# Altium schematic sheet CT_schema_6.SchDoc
size 385 x 355 mm
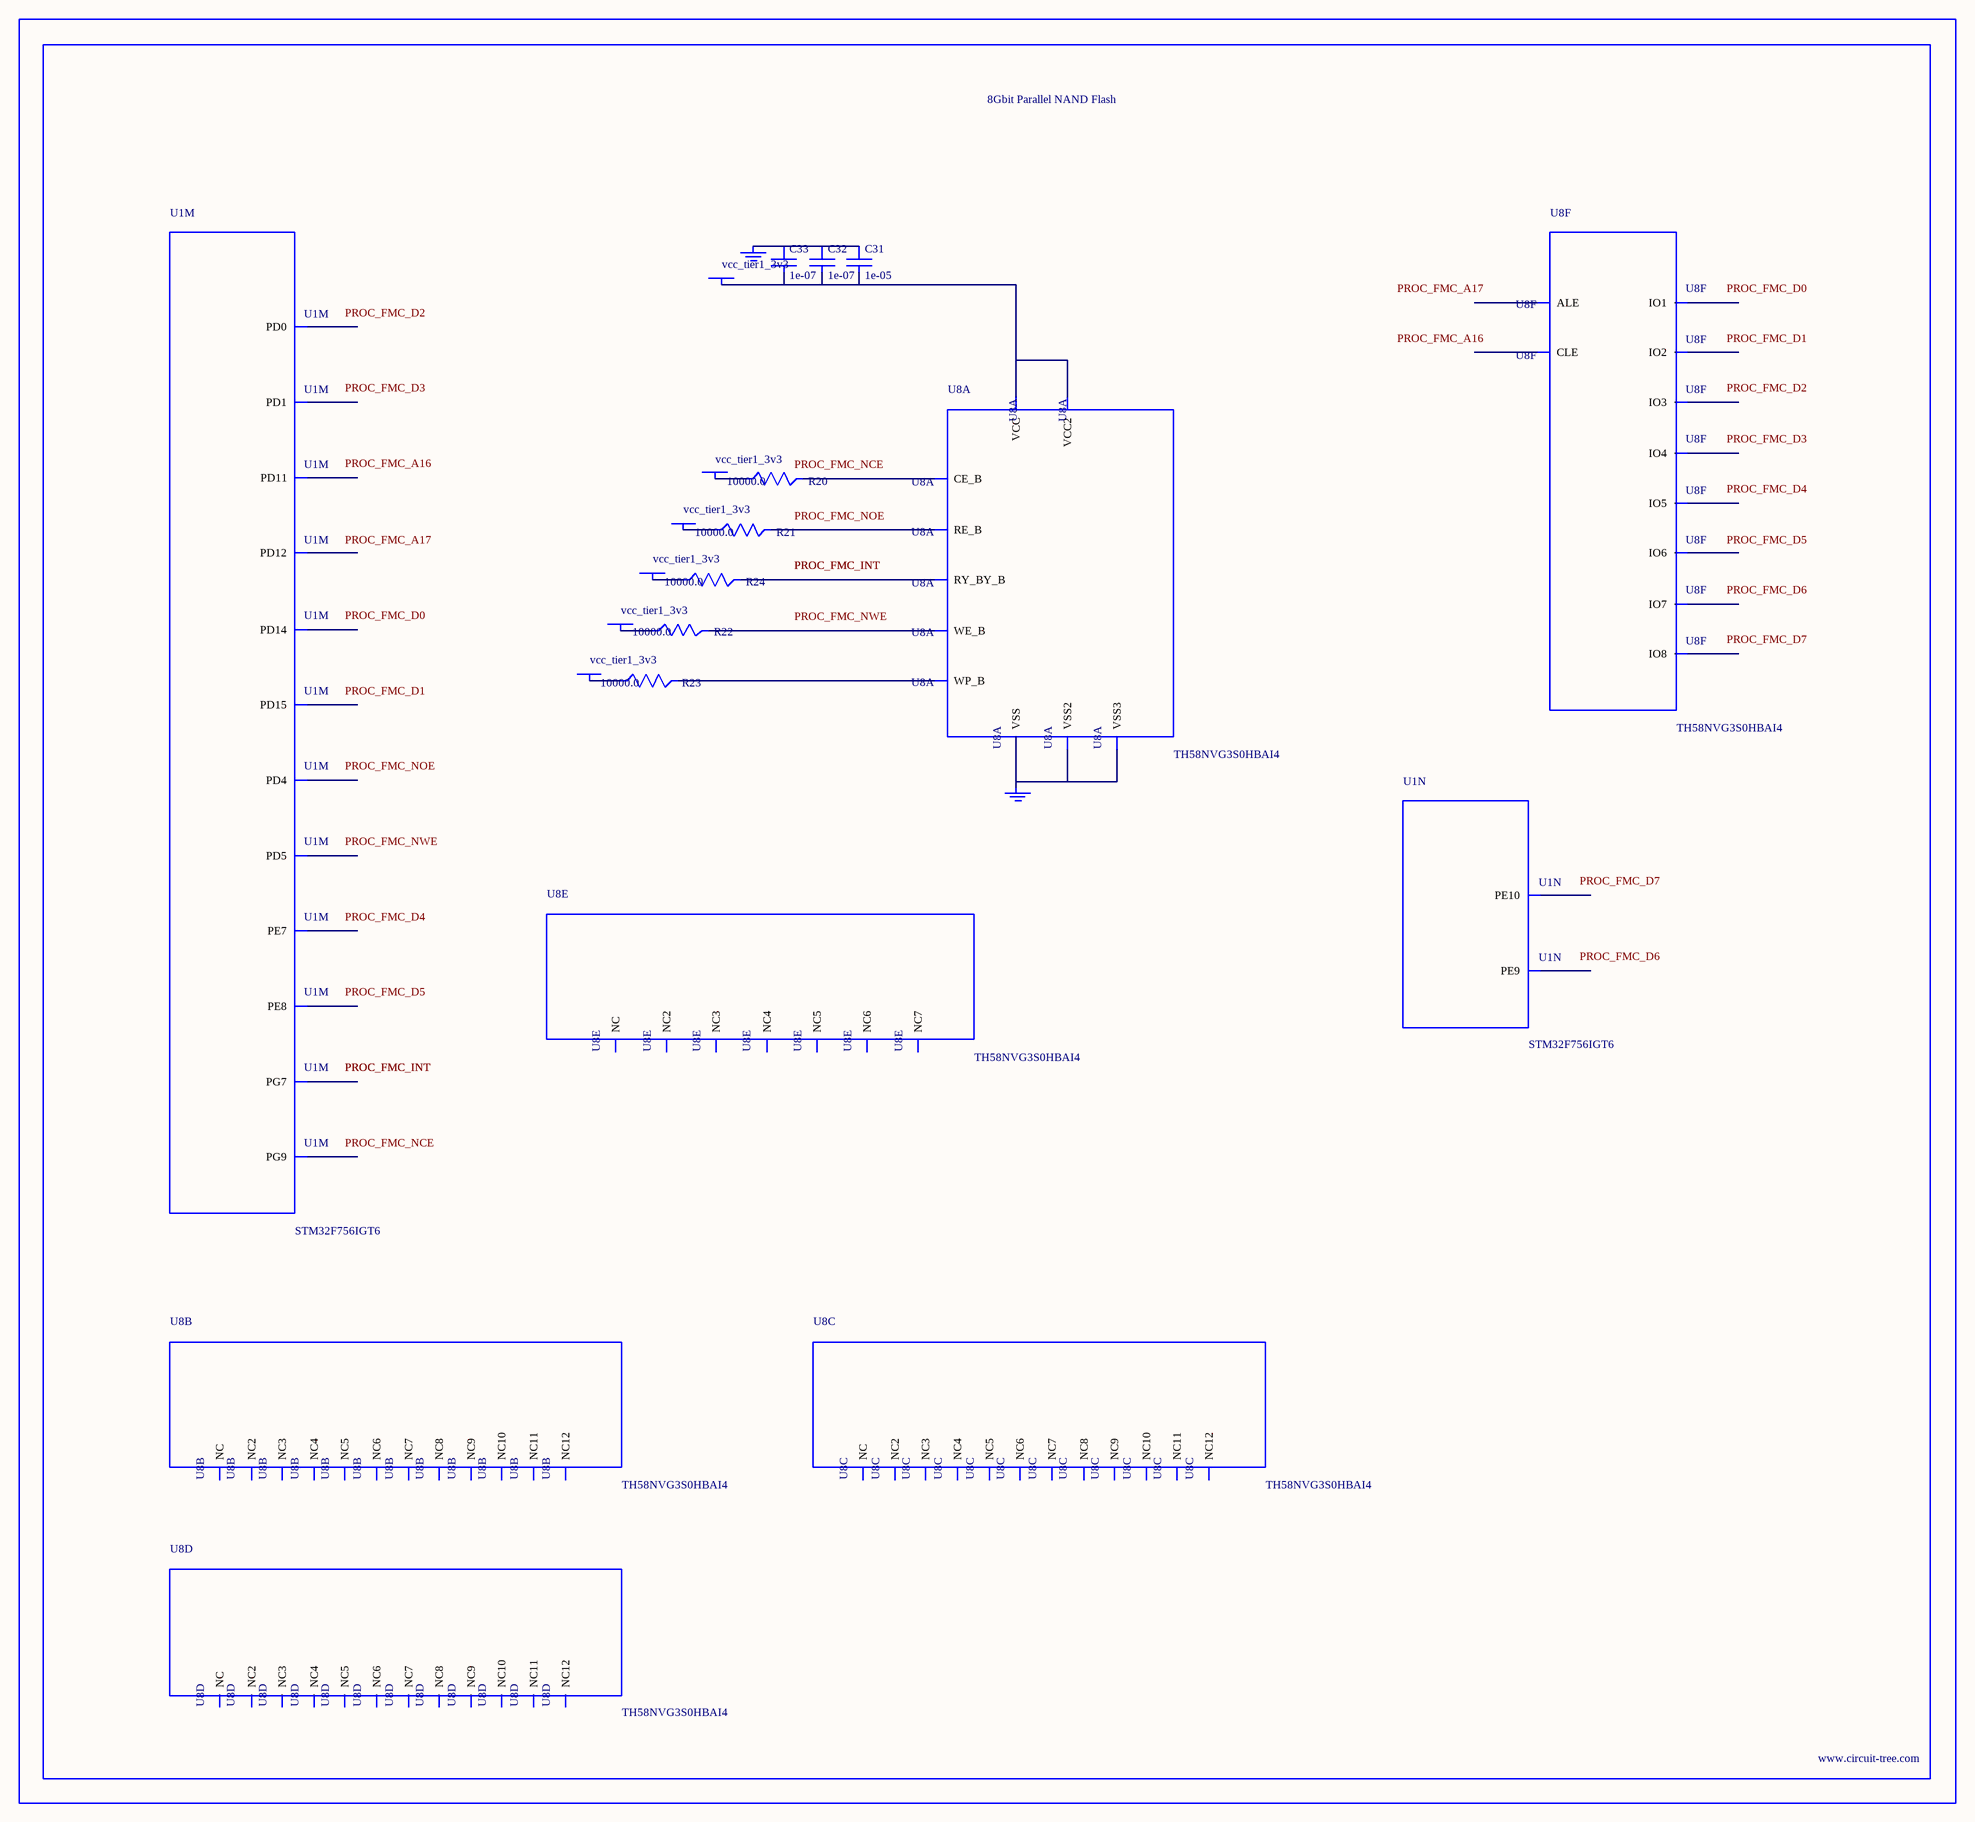
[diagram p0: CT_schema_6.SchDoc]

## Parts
BORDER5  (no value)
C31  1e-05  [C0805]
C32  1e-07  [C0402]
C33  1e-07  [C0402]
GND_INSTANCE_5_0  (no value)
GND_INSTANCE_5_1  (no value)
POWER_INSTANCE_5_0  vcc_tier1_3v3
POWER_INSTANCE_5_1  vcc_tier1_3v3
POWER_INSTANCE_5_2  vcc_tier1_3v3
POWER_INSTANCE_5_3  vcc_tier1_3v3
POWER_INSTANCE_5_4  vcc_tier1_3v3
POWER_INSTANCE_5_5  vcc_tier1_3v3
R20  10000.0  [R0603]
R21  10000.0  [R0603]
R22  10000.0  [R0603]
R23  10000.0  [R0603]
R24  10000.0  [R0603]
U1  STM32F756IGT6  [LQFP176]  (parts M,N of 14)
U8  TH58NVG3S0HBAI4  [TH58NVG3S0HBAI4]  (parts A,B,C,D,E,F of 6)

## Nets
NetC31_1: C31.1 C32.1 C33.1 GND_INSTANCE_5_0.0(GND)
NetC31_2: C31.2 C32.2 C33.2 POWER_INSTANCE_5_5.0(PWR) U8.H8(VCC) U8.J6(VCC2)
NetGND_INSTANCE_5_1_0: GND_INSTANCE_5_1.0(GND) U8.C5(VSS) U8.K3(VSS2) U8.K8(VSS3)
NetPOWER_INSTANCE_5_0_0: POWER_INSTANCE_5_0.0(PWR) R20.1
NetPOWER_INSTANCE_5_1_0: POWER_INSTANCE_5_1.0(PWR) R21.1
NetPOWER_INSTANCE_5_2_0: POWER_INSTANCE_5_2.0(PWR) R22.1
NetPOWER_INSTANCE_5_3_0: POWER_INSTANCE_5_3.0(PWR) R23.1
NetPOWER_INSTANCE_5_4_0: POWER_INSTANCE_5_4.0(PWR) R24.1
NetR20_2: R20.2 U8.C6(CE_B)
NetR21_2: R21.2 U8.D4(RE_B)
NetR22_2: R22.2 U8.C7(WE_B)
NetR23_2: R23.2 U8.C3(WP_B)
NetR24_2: R24.2 U8.C8(RY_BY_B)

Not connected (* = marked no-connect by the designer): U1 68(PE7) 69(PE8) 70(PE9) 73(PE10) 99(PD11) 100(PD12) 104(PD14) 105(PD15) 111(PG7) 142(PD0) 143(PD1) 146(PD4) 147(PD5) 152(PG9); U8 A1(NC) A2(NC3) A9(NC4) A10(NC2) B1(NC5) B9(NC7) B10(NC6) C4(ALE) D3(NC8) D5(CLE) D6(NC9) D7(NC10) D8(NC11) E3(NC12) E4(NC) E5(NC2) E6(NC3) E7(NC4) E8(NC5) F3(NC6) F4(NC7) F5(NC8) F6(NC9) F7(NC10) F8(NC11) G3(NC12) G4(NC) G5(NC2) G6(NC3) G7(NC4) G8(NC5) H3(NC6) H4(IO1) H5(NC7) H6(NC8) H7(NC9) J3(NC10) J4(IO2) J5(NC11) J7(IO6) J8(IO8) K4(IO3) K5(IO4) K6(IO5) K7(IO7) L1(NC12) L2(NC2) L9(NC3) L10(NC) M1(NC4) M2(NC6) M9(NC7) M10(NC5)

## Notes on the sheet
- Labels drawn without touching a wire or pin: PROC_FMC_A16, PROC_FMC_A17, PROC_FMC_D0, PROC_FMC_D1, PROC_FMC_D2, PROC_FMC_D3, PROC_FMC_D4, PROC_FMC_D5, PROC_FMC_D6, PROC_FMC_D7, PROC_FMC_NCE, PROC_FMC_NOE, PROC_FMC_NWE

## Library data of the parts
BORDER5 = BORDER_PAGE5
C31 = C0805C106K8RACTU
C32 C33 = C0402C104K3RACTU
GND_INSTANCE_5_0 GND_INSTANCE_5_1 = GND
POWER_INSTANCE_5_0-POWER_INSTANCE_5_5 = PWR
R20-R24 = RC0603JR-0710KL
